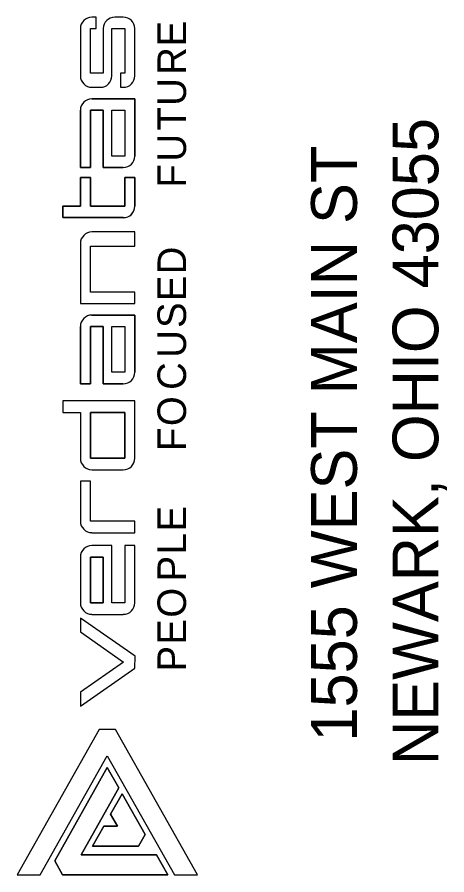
# Model space of a CAD drawing. Extents: x 0 to 37.7, y 0 to 22.
# Drawn here: x 36.848 to 37.675, y 2.576 to 4.227 of the extents above; entities that cross this region are included whole.
import ezdxf

# ---------------------------------------------------------------- set-up
doc = ezdxf.new("R2010")
doc.units = 0
for name, color, linetype in [('CS-ANNO-TTLB-LOGO', 7, 'Continuous'), ('Default', 7, 'Continuous'), ('SH_Text', 7, 'Continuous')]:
    doc.layers.add(name, color=color, linetype=linetype)

msp = doc.modelspace()

# ---------------------------------------------------------------- linework, layer by layer
at = {"layer": 'CS-ANNO-TTLB-LOGO'}
for p, q in [((36.9998, 4.2267), (36.9916, 4.2267)), ((37.0522, 4.2267), (37.0357, 4.2267)), ((36.9695, 4.2047), (36.9695, 4.1137)), ((37.0743, 4.1137), (37.0743, 4.2047)), ((36.9916, 4.0917), (37.0081, 4.0917)), ((36.9695, 3.9373), (36.9695, 4.0476)), ((36.9695, 3.5211), (36.9695, 3.6313)), ((36.9916, 3.3557), (37.0522, 3.3557)), ((37.0743, 3.0994), (37.0743, 3.2096)), ((36.9695, 3.1876), (36.9695, 3.0994)), ((36.9916, 3.0773), (37.0522, 3.0773))]:
    msp.add_line(p, q, dxfattribs=at)
for points in [[(37.0136, 4.2047), (37.0136, 4.1192), (36.9888, 4.1192), (36.9888, 4.2047), (36.9998, 4.2047), (36.9998, 4.2267)], [(37.0302, 4.1137), (37.0302, 4.2047), (37.055, 4.2047), (37.055, 4.1192), (37.0467, 4.1192), (37.0467, 4.0917), (37.0522, 4.0917)], [(36.9916, 4.0696), (37.0743, 4.0696), (37.0743, 3.9594)], [(37.0522, 3.9373), (37.0136, 3.9373), (37.0136, 4.0476), (36.9888, 4.0476), (36.9888, 3.9373), (36.9695, 3.9373)], [(36.9355, 3.8628), (36.9695, 3.8628), (36.9695, 3.918), (36.9888, 3.918), (36.9888, 3.8628), (37.055, 3.8628), (37.055, 3.918), (37.0743, 3.918), (37.0743, 3.8628)], [(37.0522, 3.8408), (36.9355, 3.8408), (36.9355, 3.8628)], [(37.0743, 3.7857), (37.0743, 3.8132), (36.9916, 3.8132)], [(36.9695, 3.7912), (36.9695, 3.6754), (37.0743, 3.6754), (37.0743, 3.6975), (36.9888, 3.6975), (36.9888, 3.7857), (37.0743, 3.7857)], [(36.9916, 3.6534), (37.0743, 3.6534), (37.0743, 3.5431)], [(37.0522, 3.5211), (37.0136, 3.5211), (37.0136, 3.6313), (36.9888, 3.6313), (36.9888, 3.5211), (36.9695, 3.5211)], [(36.9355, 3.488), (36.9355, 3.4659), (36.9695, 3.4659), (36.9695, 3.3777)], [(37.0743, 3.3777), (37.0743, 3.488), (36.9355, 3.488)], [(37.0743, 3.2565), (36.9888, 3.2565), (36.9888, 3.3336), (36.9695, 3.3336), (36.9695, 3.2565)], [(36.9916, 3.2344), (37.0743, 3.2344), (37.0743, 3.2565)], [(37.0743, 3.2096), (37.055, 3.2096), (37.055, 3.0994), (37.0302, 3.0994), (37.0302, 3.2096), (36.9916, 3.2096)]]:
    msp.add_lwpolyline(points, dxfattribs=at)
for points in [[(37.0302, 4.0476), (37.055, 4.0476), (37.055, 3.9594), (37.0302, 3.9594)], [(37.0302, 3.6313), (37.055, 3.6313), (37.055, 3.5431), (37.0302, 3.5431)], [(36.9888, 3.4659), (36.9888, 3.3777), (37.055, 3.3777), (37.055, 3.4659)], [(37.0136, 3.1876), (36.9888, 3.1876), (36.9888, 3.0994), (37.0136, 3.0994)], [(37.0523, 2.9854), (36.9695, 2.9275), (36.9695, 2.9006), (37.0743, 2.9739), (37.0747, 2.9966), (36.97, 3.07), (36.9695, 3.0434)]]:
    msp.add_lwpolyline(points, close=True, dxfattribs=at)
for centre, radius, start, end in [((36.9916, 4.2047), 0.022, 90, 180), ((37.0357, 4.2047), 0.022, 90, 180), ((37.0522, 4.2047), 0.0221, 360, 90), ((36.9916, 4.1137), 0.022, 180, 270), ((37.0081, 4.1137), 0.022, 270, 0), ((37.0522, 4.1137), 0.022, 270, 0), ((36.9916, 4.0476), 0.022, 90, 180), ((37.0522, 3.9594), 0.0221, 270, 360), ((37.0522, 3.8628), 0.0221, 270, 360), ((36.9916, 3.7912), 0.022, 90, 180), ((36.9916, 3.6313), 0.022, 90, 180), ((37.0522, 3.5431), 0.0221, 270, 360), ((36.9916, 3.3777), 0.022, 180, 270), ((37.0522, 3.3777), 0.022, 270, 0), ((36.9916, 3.2565), 0.022, 180, 270), ((36.9916, 3.1876), 0.022, 90, 180), ((36.9916, 3.0994), 0.022, 180, 270), ((37.0522, 3.0994), 0.022, 270, 0)]:
    msp.add_arc(centre, radius, start, end, dxfattribs=at)
at = {"layer": 'Default'}
for p, q in [((37.0522, 4.2267), (37.0357, 4.2267)), ((36.9695, 4.2047), (36.9695, 4.1137)), ((37.0743, 4.1137), (37.0743, 4.2047)), ((36.9916, 4.0917), (37.0081, 4.0917)), ((36.9916, 3.3557), (37.0522, 3.3557)), ((36.9695, 3.1876), (36.9695, 3.0994)), ((36.9916, 3.0773), (37.0522, 3.0773)), ((36.92, 2.6031), (37.0213, 2.7826)), ((37.0213, 2.7826), (37.0434, 2.7433)), ((37.0434, 2.7433), (36.9708, 2.6145)), ((36.9708, 2.6145), (37.1161, 2.6145)), ((37.1161, 2.6145), (37.1379, 2.5759)), ((36.9353, 2.5759), (36.92, 2.6031)), ((37.1379, 2.5759), (36.9353, 2.5759))]:
    msp.add_line(p, q, dxfattribs=at)
for points in [[(37.0136, 4.2047), (37.0136, 4.1192), (36.9888, 4.1192), (36.9888, 4.2047), (36.9998, 4.2047), (36.9998, 4.2267), (36.9916, 4.2267)], [(37.0302, 4.1137), (37.0302, 4.2047), (37.055, 4.2047), (37.055, 4.1192), (37.0467, 4.1192), (37.0467, 4.0917), (37.0522, 4.0917)], [(37.0743, 3.9594), (37.0743, 4.0696), (36.9916, 4.0696)], [(36.9695, 4.0476), (36.9695, 3.9373), (36.9888, 3.9373), (36.9888, 4.0476), (37.0136, 4.0476), (37.0136, 3.9373), (37.0522, 3.9373)], [(37.0743, 3.8628), (37.0743, 3.918), (37.055, 3.918), (37.055, 3.8628), (36.9888, 3.8628), (36.9888, 3.918), (36.9695, 3.918), (36.9695, 3.8628), (36.9355, 3.8628), (36.9355, 3.8408), (37.0522, 3.8408)], [(36.9695, 3.7912), (36.9695, 3.6754), (37.0743, 3.6754), (37.0743, 3.6975), (36.9888, 3.6975), (36.9888, 3.7857), (37.0743, 3.7857), (37.0743, 3.8132), (36.9916, 3.8132)], [(37.0743, 3.5431), (37.0743, 3.6534), (36.9916, 3.6534)], [(36.9695, 3.6313), (36.9695, 3.5211), (36.9888, 3.5211), (36.9888, 3.6313), (37.0136, 3.6313), (37.0136, 3.5211), (37.0522, 3.5211)], [(37.0743, 3.3777), (37.0743, 3.488), (36.9355, 3.488), (36.9355, 3.4659), (36.9695, 3.4659), (36.9695, 3.3777)], [(36.9916, 3.2344), (37.0743, 3.2344), (37.0743, 3.2565), (36.9888, 3.2565), (36.9888, 3.3336), (36.9695, 3.3336), (36.9695, 3.2565)], [(37.0743, 3.0994), (37.0743, 3.2096), (37.055, 3.2096), (37.055, 3.0994), (37.0302, 3.0994), (37.0302, 3.2096), (36.9916, 3.2096)]]:
    msp.add_lwpolyline(points, dxfattribs=at)
for points in [[(37.055, 4.0476), (37.055, 3.9594), (37.0302, 3.9594), (37.0302, 4.0476)], [(37.055, 3.6313), (37.055, 3.5431), (37.0302, 3.5431), (37.0302, 3.6313)], [(36.9888, 3.4659), (37.055, 3.4659), (37.055, 3.3777), (36.9888, 3.3777)], [(37.0136, 3.1876), (37.0136, 3.0994), (36.9888, 3.0994), (36.9888, 3.1876)], [(36.9695, 2.9275), (36.9695, 2.9006), (37.0743, 2.9739), (37.0747, 2.9966), (36.97, 3.07), (36.9695, 3.0434), (37.0523, 2.9854)], [(37.0213, 2.805), (37.1505, 2.5759), (37.1948, 2.5759), (37.0371, 2.8555), (37.0055, 2.8555), (36.8477, 2.5759), (36.892, 2.5759)], [(36.892, 2.5759), (37.0213, 2.805), (37.1505, 2.5759), (37.1948, 2.5759), (37.0371, 2.8555), (37.0055, 2.8555), (36.8477, 2.5759)], [(36.92, 2.6031), (36.9353, 2.5759), (37.1379, 2.5759), (37.1161, 2.6145), (36.9708, 2.6145), (37.0434, 2.7433), (37.0213, 2.7826)], [(37.0145, 2.6696), (36.9928, 2.631), (37.0814, 2.631), (37.0941, 2.6535), (37.0498, 2.7321), (37.0276, 2.6928), (37.0407, 2.6696)], [(37.0145, 2.6696), (37.0407, 2.6696), (37.0276, 2.6928), (37.0498, 2.7321), (37.0941, 2.6535), (37.0814, 2.631), (36.9928, 2.631)]]:
    msp.add_lwpolyline(points, close=True, dxfattribs=at)
for centre, start, end in [((36.9916, 4.2047), 90, 180), ((37.0357, 4.2047), 90, 180), ((37.0522, 4.2047), 360, 90), ((36.9916, 4.1137), 180, 270), ((37.0081, 4.1137), 270, 0), ((37.0522, 4.1137), 270, 0), ((36.9916, 4.0476), 90, 180), ((37.0522, 3.9594), 270, 0), ((37.0522, 3.8628), 270, 0), ((36.9916, 3.7912), 90, 180), ((36.9916, 3.6313), 90, 180), ((37.0522, 3.5431), 270, 0), ((36.9916, 3.3777), 180, 270), ((37.0522, 3.3777), 270, 0), ((36.9916, 3.2565), 180, 270), ((36.9916, 3.1876), 90, 180), ((36.9916, 3.0994), 180, 270), ((37.0522, 3.0994), 270, 0)]:
    msp.add_arc(centre, 0.022, start, end, dxfattribs=at)

# ---------------------------------------------------------------- texts
for s, p in [('E', (37.173, 4.1705)), ('R', (37.173, 4.1158)), ('U', (37.173, 4.0561)), ('T', (37.173, 4.0085)), ('U', (37.173, 3.9488)), ('F', (37.173, 3.8986)), ('D', (37.173, 3.7318)), ('E', (37.173, 3.6801)), ('S', (37.173, 3.6285)), ('U', (37.173, 3.5712)), ('C', (37.173, 3.5093)), ('O', (37.173, 3.4397)), ('F', (37.173, 3.3917)), ('E', (37.173, 3.2368)), ('L', (37.173, 3.1925)), ('P', (37.173, 3.1407)), ('O', (37.173, 3.0709)), ('E', (37.173, 3.019)), ('P', (37.173, 2.9673))]:
    msp.add_text(s, height=0.0551, rotation=90, dxfattribs=at).set_placement(p)
at = {"layer": 'SH_Text'}
for s, p in [('NEWARK, OHIO 43055', (37.6588, 2.7872)), ('1555 WEST MAIN ST', (37.502, 2.8324))]:
    msp.add_text(s, height=0.0882, rotation=90, dxfattribs=at).set_placement(p)

doc.saveas('drawing.dxf')
